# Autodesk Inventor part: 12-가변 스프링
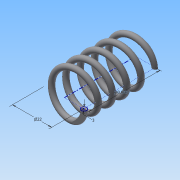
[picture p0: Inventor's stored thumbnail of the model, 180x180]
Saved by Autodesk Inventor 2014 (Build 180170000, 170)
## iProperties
Created: 2015-09
Part Number: 12-가변 스프링
Material: 강철, 탄소
Document SubType Name: Modeling
Designer: study
Density: 7.87 g/cm^3
Appearance: 반연마
Mass: 18.9154 g
Surface Area: 32.5802 cm^2
Volume: 2.40348 cm^3
Author: study
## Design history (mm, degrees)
sketch "스케치1"
  geometry: L1 (0, 0)-(11, 0); L2 (11, 0)-(11, 40.095); L3 (11, 40.095)-(0, 40.095); L4 (0, 40.095)-(0, 0); C1 r 1.5 at (11, 0)
  constraints: 8 end point, 2 parallel, 1 centre point, 1 coincident, 1 horizontal, 1 perpendicular
  dimensions: "d0" = 22 diameter of L2 L4; "d1" = 40.0955 distance of L1.end L2.end (derived); "d2" = 3 diameter of C1
feature "코일1" sketch "스케치1" pitch "d3" = 10; turns "d5" = 5; dims "d4" = 40.0955 (= d1), "d6" = 0, angle "d7" = 90 deg, angle "d8" = 90 deg, "d9" = 0, "d10" = 0
node "작업 평면1"
sketch "스케치2"
  geometry: L1 (-12.5, 0)-(-9.5, 0) reference; L2 (-12.5, 0)-(-9.5, 0) reference; 1 further point
  constraints: 2 horizontal alignment
extrude "돌출1" cut sketch "스케치2" stored distance "d12" = 10; taper "d13" = 0 deg
node "작업 평면2"
sketch "스케치3"
  geometry: L1 (-9.5, 0)-(-12.5, 0) reference; 1 further point
  constraints: 1 horizontal alignment
extrude "돌출2" cut sketch "스케치3" stored distance "d15" = 10; taper "d16" = 0 deg
node "솔리드1"
node "절단 모서리 투영1"
node "절단 모서리 투영2"
node "절단 모서리 투영3"
other parameters: "d11" = 0, "d14" = 40.0955 (= d1)
